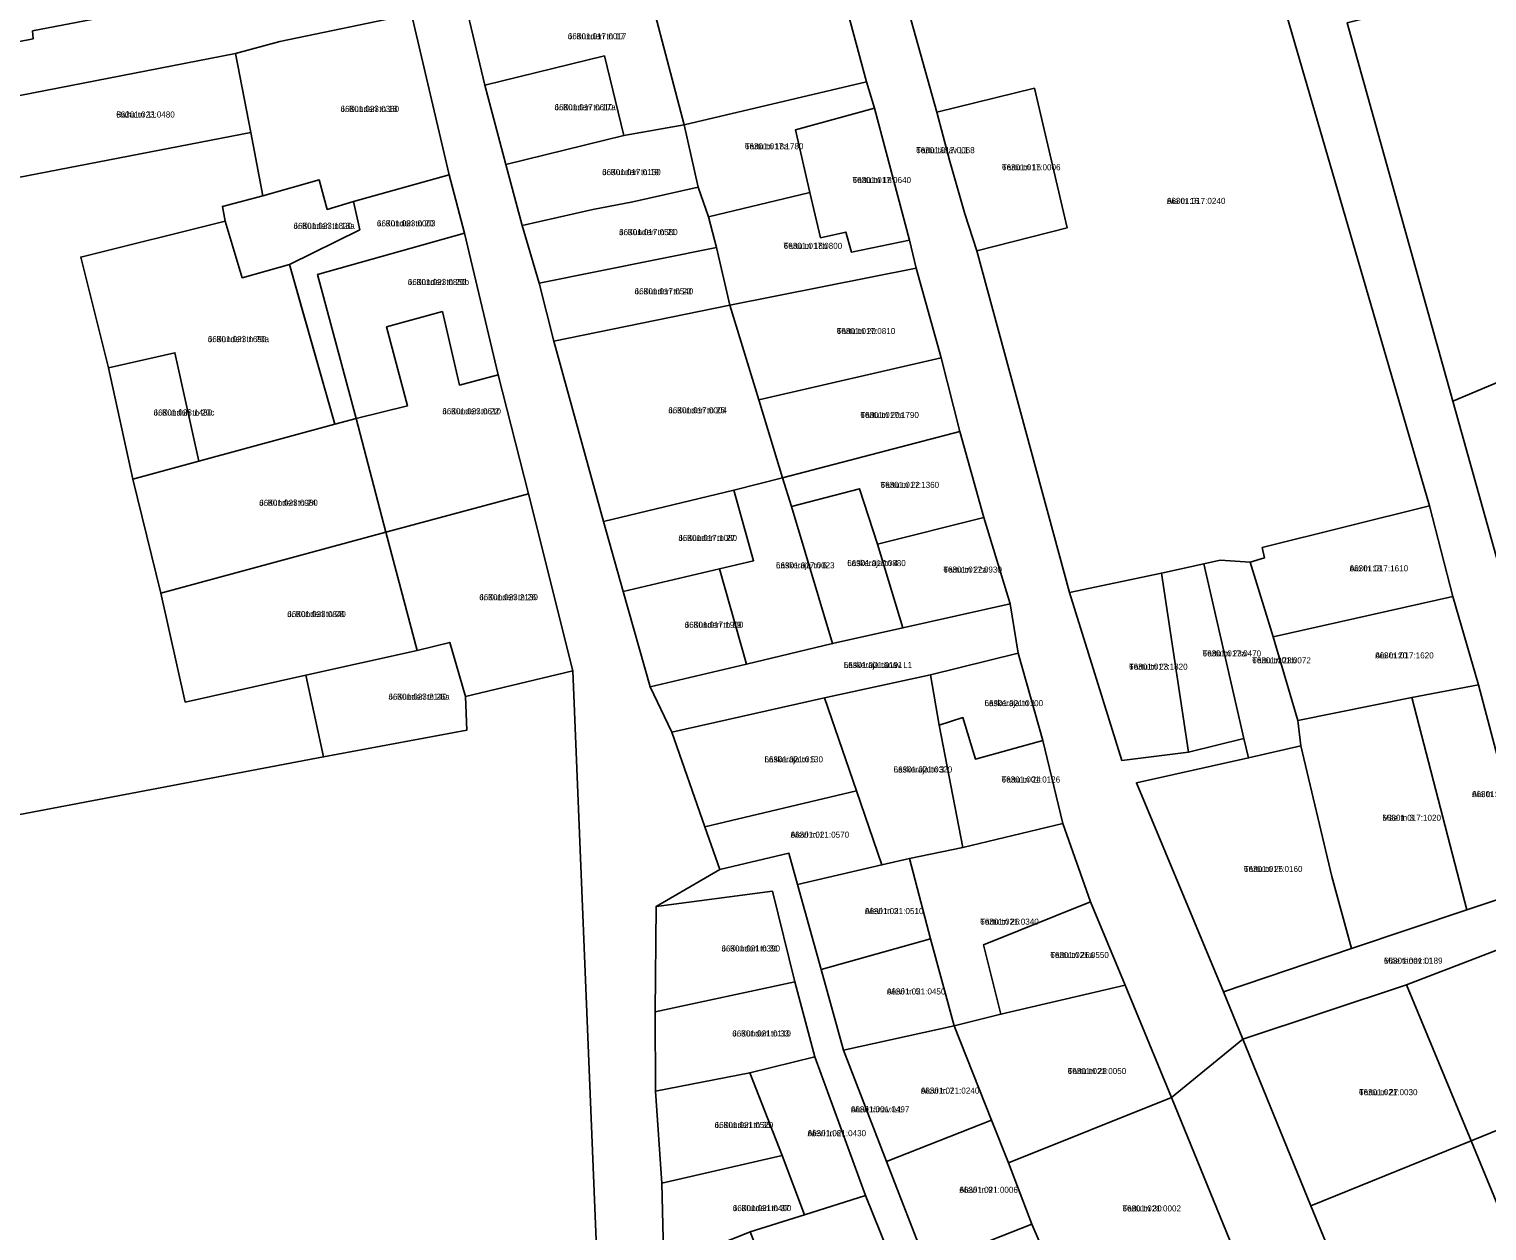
# Model space of a CAD drawing. Extents: x 632278 to 636344, y 6578401 to 6583362.
# Drawn here: x 634102 to 634463, y 6579613.5 to 6579911.1 of the extents above; entities that cross this region are included whole.
import ezdxf

# ---------------------------------------------------------------- set-up
doc = ezdxf.new("R2010")
doc.units = 0
for name, color, linetype in [('L_AADRESS', 7, 'Continuous'), ('PIIR', 7, 'Continuous'), ('TUNNUS', 7, 'Continuous')]:
    doc.layers.add(name, color=color, linetype=linetype)

msp = doc.modelspace()

# ---------------------------------------------------------------- linework, layer by layer
at = {"layer": 'PIIR'}
for points in [[(634134.84, 6579916.78), (634102.89, 6579910.69), (634103.07, 6579908.73), (633996.04, 6579887.8), (633922.52, 6579873.28), (633909.78, 6579870.79), (633882.41, 6579868.19), (633860.88, 6579866.54), (633901.14, 6579996.08)], [(634428.41, 6579912.71), (634454.6, 6579819), (634466.88, 6579774.98), (634471.39, 6579758.77), (634473.81, 6579750.16), (634478.25, 6579733.1), (634483.64, 6579714.01), (634474.24, 6579698.34), (634460.96, 6579748.73), (634454.56, 6579770.62), (634448.82, 6579793.07), (634399.59, 6579962.17)], [(634318.74, 6579919.57), (634326.8, 6579890.54), (634329.99, 6579878.64), (634333.71, 6579865.41), (634336.71, 6579856.24), (634359.7, 6579771.6), (634372.64, 6579730.02), (634389.13, 6579732.08), (634402.81, 6579735.45), (634404.02, 6579730.64), (634376.23, 6579724.48), (634397.83, 6579672.68), (634402.59, 6579661.02), (634384.96, 6579646.58), (634373.45, 6579674.32), (634364.9, 6579695.03), (634357.98, 6579714.38), (634353.05, 6579734.97), (634346.92, 6579756.57), (634344.96, 6579768.8), (634338.49, 6579790.21), (634332.49, 6579811.45), (634327.93, 6579829.68), (634321.67, 6579851.92), (634320.07, 6579858.85), (634311.36, 6579891.55), (634309.43, 6579898.1), (634297.75, 6579941.29)], [(634208.5, 6579923.96), (634214.86, 6579897.24), (634220.1, 6579877.59), (634224.11, 6579862.47), (634228.31, 6579848.23), (634232.01, 6579833.88), (634244.23, 6579789.21), (634249.14, 6579771.82), (634255.8, 6579748.25), (634261.17, 6579737.02), (634269.37, 6579713.57), (634273.06, 6579703.04), (634257.3, 6579693.87), (634257.06, 6579667.79), (634257.18, 6579648.14), (634258.69, 6579625.33), (634259.21, 6579604.65)], [(634257.85, 6579257.23), (634244.2, 6579568.83), (634236.65, 6579752.17), (634225.68, 6579796.06), (634218.2, 6579825.48), (634209.86, 6579860.59), (634206.07, 6579875.04), (634196.71, 6579914.79)], [(634486.34, 6579385.27), (634483.98, 6579405.6), (634478.47, 6579419.65), (634466.61, 6579447.62), (634455.32, 6579474.96), (634438.73, 6579515.02), (634431.09, 6579534.13), (634422.81, 6579554.17), (634417.18, 6579567.08), (634402.17, 6579603.44), (634400.91, 6579607.29), (634384.96, 6579646.58), (634402.59, 6579661.02), (634419.47, 6579619.73), (634437.36, 6579576.09), (634451.81, 6579540.83), (634467.43, 6579502.09), (634483.75, 6579461.64), (634500.06, 6579421.57), (634505.81, 6579408.32), (634509.22, 6579376.05)]]:
    msp.add_lwpolyline(points, dxfattribs=at)
for points in [[(634382.42, 6579776.42), (634359.7, 6579771.6), (634336.71, 6579856.24), (634359.1, 6579861.95), (634351, 6579896.5), (634326.8, 6579890.54), (634318.74, 6579919.57), (634352.27, 6579930.21), (634346.01, 6579951.31), (634399.59, 6579962.17), (634448.82, 6579793.07), (634407.4, 6579782.73), (634407.97, 6579780.21), (634404.38, 6579779.12), (634397, 6579779.58), (634392.91, 6579778.67)], [(634557.59, 6579862.31), (634500.94, 6579838.5), (634454.6, 6579819), (634428.41, 6579912.71), (634517.24, 6579934.89), (634533.05, 6579938.89), (634548.8, 6579942.83), (634554.62, 6579929.91), (634556.45, 6579925.73), (634570.22, 6579894.2), (634579.92, 6579871.87)], [(634252.46, 6579932.45), (634297.75, 6579941.29), (634309.43, 6579898.1), (634264.28, 6579887.44)], [(634208.5, 6579923.96), (634252.46, 6579932.45), (634264.28, 6579887.44), (634249.32, 6579884.78), (634244.48, 6579904.5), (634214.86, 6579897.24)], [(634192.49, 6579928.96), (634196.71, 6579914.79), (634164.1, 6579908.1), (634153.15, 6579905.08), (634090.32, 6579892.84), (634029.4, 6579880.96), (634021.71, 6579879.31), (633974.52, 6579871.4), (633934.61, 6579863.15), (633916.66, 6579859.34), (633920.26, 6579867.83), (633922.52, 6579873.28), (633996.04, 6579887.8), (634103.07, 6579908.73), (634102.89, 6579910.69), (634134.84, 6579916.78)], [(634182.33, 6579868.42), (634175.85, 6579866.48), (634173.86, 6579873.76), (634159.93, 6579869.82), (634156.91, 6579885.52), (634153.15, 6579905.08), (634164.1, 6579908.1), (634196.71, 6579914.79), (634206.07, 6579875.04)], [(634090.32, 6579892.84), (634153.15, 6579905.08), (634156.91, 6579885.52), (634094.14, 6579873.38)], [(634214.86, 6579897.24), (634244.48, 6579904.5), (634249.32, 6579884.78), (634220.1, 6579877.59)], [(634267.75, 6579871.97), (634264.28, 6579887.44), (634309.43, 6579898.1), (634311.36, 6579891.55), (634291.8, 6579886.18), (634295.39, 6579870.63), (634270.28, 6579864.63)], [(634326.8, 6579890.54), (634351, 6579896.5), (634359.1, 6579861.95), (634336.71, 6579856.24), (634333.71, 6579865.41), (634329.99, 6579878.64)], [(634311.36, 6579891.55), (634320.07, 6579858.85), (634305.68, 6579855.88), (634304.28, 6579860.86), (634298.03, 6579859.46), (634295.39, 6579870.63), (634291.8, 6579886.18)], [(633987.22, 6579804.58), (634000.93, 6579805.97), (634034.81, 6579812.6), (634023.21, 6579872.13), (634021.71, 6579879.31), (634029.4, 6579880.96), (634033.39, 6579860.17), (634043.31, 6579862.03), (634042.99, 6579863.24), (634094.14, 6579873.38), (634156.91, 6579885.52), (634159.93, 6579869.82), (634149.88, 6579867.2), (634150.61, 6579863.55), (634114.83, 6579854.66), (634121.68, 6579827.26), (634127.73, 6579799.67), (634134.62, 6579771.46), (634140.69, 6579744.46), (634170.57, 6579751.11), (634174.97, 6579730.89), (634055.35, 6579708.17), (634050.52, 6579730.42), (634002.77, 6579717.78)], [(634220.1, 6579877.59), (634249.32, 6579884.78), (634264.28, 6579887.44), (634267.75, 6579871.97), (634251.55, 6579868.38), (634241.63, 6579866.44), (634224.11, 6579862.47)], [(634206.07, 6579875.04), (634209.86, 6579860.59), (634173.43, 6579850.38), (634183.06, 6579814.7), (634177.74, 6579813.26), (634166.48, 6579852.84), (634183.89, 6579861.43), (634182.33, 6579868.42)], [(634150.61, 6579863.55), (634149.88, 6579867.2), (634159.93, 6579869.82), (634173.86, 6579873.76), (634175.85, 6579866.48), (634182.33, 6579868.42), (634183.89, 6579861.43), (634166.48, 6579852.84), (634154.79, 6579849.55)], [(634224.11, 6579862.47), (634241.63, 6579866.44), (634251.55, 6579868.38), (634267.75, 6579871.97), (634270.28, 6579864.63), (634272.24, 6579857.03), (634228.31, 6579848.23)], [(634272.24, 6579857.03), (634270.28, 6579864.63), (634295.39, 6579870.63), (634298.03, 6579859.46), (634304.28, 6579860.86), (634305.68, 6579855.88), (634320.07, 6579858.85), (634321.67, 6579851.92), (634275.58, 6579842.77)], [(634138.12, 6579830.98), (634121.68, 6579827.26), (634114.83, 6579854.66), (634150.61, 6579863.55), (634154.79, 6579849.55), (634166.48, 6579852.84), (634169.65, 6579841.7), (634177.74, 6579813.26), (634144.05, 6579804.11)], [(634195.71, 6579817.81), (634183.06, 6579814.7), (634173.43, 6579850.38), (634209.86, 6579860.59), (634218.2, 6579825.48), (634208.62, 6579822.97), (634204.38, 6579841.18), (634190.54, 6579837.41)], [(634275.58, 6579842.77), (634232.01, 6579833.88), (634228.31, 6579848.23), (634272.24, 6579857.03)], [(634275.58, 6579842.77), (634321.67, 6579851.92), (634327.93, 6579829.68), (634282.76, 6579819.29)], [(634232.01, 6579833.88), (634275.58, 6579842.77), (634282.76, 6579819.29), (634288.57, 6579799.96), (634276.53, 6579796.91), (634244.23, 6579789.21)], [(634204.38, 6579841.18), (634208.62, 6579822.97), (634218.2, 6579825.48), (634225.68, 6579796.06), (634190.4, 6579786.55), (634183.06, 6579814.7), (634195.71, 6579817.81), (634190.54, 6579837.41)], [(634454.6, 6579819), (634500.94, 6579838.5), (634517.72, 6579795.77), (634466.88, 6579774.98)], [(634121.68, 6579827.26), (634138.12, 6579830.98), (634144.05, 6579804.11), (634127.73, 6579799.67)], [(634282.76, 6579819.29), (634327.93, 6579829.68), (634332.49, 6579811.45), (634288.57, 6579799.96)], [(634127.73, 6579799.67), (634144.05, 6579804.11), (634177.74, 6579813.26), (634183.06, 6579814.7), (634190.4, 6579786.55), (634134.62, 6579771.46)], [(634307.65, 6579797.31), (634290.81, 6579792.93), (634288.57, 6579799.96), (634332.49, 6579811.45), (634338.49, 6579790.21), (634312.09, 6579783.58)], [(634236.65, 6579752.17), (634244.2, 6579568.83), (634195.23, 6579557.18), (634189.1, 6579582.52), (634151.76, 6579574.54), (634002.4, 6579543.18), (633848.98, 6579582.11), (633909.28, 6579792.9), (633961.16, 6579778.11), (633970.17, 6579802.87), (633987.22, 6579804.58), (634002.77, 6579717.78), (634050.52, 6579730.42), (634055.35, 6579708.17), (634174.97, 6579730.89), (634210.42, 6579737.49), (634210.12, 6579745.81)], [(634279.65, 6579753.89), (634272.98, 6579777.46), (634281.45, 6579779.47), (634276.53, 6579796.91), (634288.57, 6579799.96), (634290.81, 6579792.93), (634301.01, 6579758.95)], [(634206.2, 6579759.23), (634198.15, 6579757.25), (634190.4, 6579786.55), (634225.68, 6579796.06), (634236.65, 6579752.17), (634210.12, 6579745.81)], [(634276.53, 6579796.91), (634281.45, 6579779.47), (634272.98, 6579777.46), (634249.14, 6579771.82), (634244.23, 6579789.21)], [(634290.81, 6579792.93), (634307.65, 6579797.31), (634312.09, 6579783.58), (634318.42, 6579762.85), (634301.01, 6579758.95)], [(634404.38, 6579779.12), (634407.97, 6579780.21), (634407.4, 6579782.73), (634448.82, 6579793.07), (634454.56, 6579770.62), (634410.09, 6579760.61)], [(634312.09, 6579783.58), (634338.49, 6579790.21), (634344.96, 6579768.8), (634318.42, 6579762.85)], [(634198.15, 6579757.25), (634170.57, 6579751.11), (634140.69, 6579744.46), (634134.62, 6579771.46), (634190.4, 6579786.55)], [(634249.14, 6579771.82), (634272.98, 6579777.46), (634279.65, 6579753.89), (634255.8, 6579748.25)], [(634359.7, 6579771.6), (634382.42, 6579776.42), (634389.13, 6579732.08), (634372.64, 6579730.02)], [(634382.42, 6579776.42), (634392.91, 6579778.67), (634402.81, 6579735.45), (634389.13, 6579732.08)], [(634402.81, 6579735.45), (634392.91, 6579778.67), (634397, 6579779.58), (634404.38, 6579779.12), (634410.09, 6579760.61), (634416.22, 6579739.94), (634416.98, 6579733.67), (634404.02, 6579730.64)], [(634410.09, 6579760.61), (634454.56, 6579770.62), (634460.96, 6579748.73), (634444.46, 6579745.56), (634416.22, 6579739.94)], [(634255.8, 6579748.25), (634279.65, 6579753.89), (634301.01, 6579758.95), (634318.42, 6579762.85), (634344.96, 6579768.8), (634346.92, 6579756.57), (634325.28, 6579751.25), (634298.98, 6579745.49), (634261.17, 6579737.02)], [(634170.57, 6579751.11), (634198.15, 6579757.25), (634206.2, 6579759.23), (634210.12, 6579745.81), (634210.42, 6579737.49), (634174.97, 6579730.89)], [(634346.92, 6579756.57), (634353.05, 6579734.97), (634336.38, 6579730.36), (634333.26, 6579740.62), (634327.42, 6579738.76), (634325.28, 6579751.25)], [(634306.91, 6579722.45), (634298.98, 6579745.49), (634325.28, 6579751.25), (634327.42, 6579738.76), (634333.27, 6579708.46), (634320.06, 6579705.69), (634313.21, 6579704.15)], [(634460.96, 6579748.73), (634474.24, 6579698.34), (634458.09, 6579693.02), (634444.46, 6579745.56)], [(634269.37, 6579713.57), (634261.17, 6579737.02), (634298.98, 6579745.49), (634306.91, 6579722.45)], [(634424.64, 6579701.3), (634416.98, 6579733.67), (634416.22, 6579739.94), (634444.46, 6579745.56), (634458.09, 6579693.02), (634429.51, 6579683.46)], [(634353.05, 6579734.97), (634357.98, 6579714.38), (634333.27, 6579708.46), (634327.42, 6579738.76), (634333.26, 6579740.62), (634336.38, 6579730.36)], [(634404.02, 6579730.64), (634416.98, 6579733.67), (634424.64, 6579701.3), (634429.51, 6579683.46), (634397.83, 6579672.68), (634376.23, 6579724.48)], [(634269.37, 6579713.57), (634306.91, 6579722.45), (634313.21, 6579704.15), (634292.32, 6579699.31), (634290.19, 6579707.02), (634273.06, 6579703.04)], [(634342.7, 6579667.14), (634331.14, 6579664.3), (634325.25, 6579685.85), (634320.06, 6579705.69), (634333.27, 6579708.46), (634357.98, 6579714.38), (634364.9, 6579695.03), (634338.37, 6579684.33)], [(634286.12, 6579697.6), (634257.3, 6579693.87), (634273.06, 6579703.04), (634290.19, 6579707.02), (634292.32, 6579699.31), (634298.16, 6579678.23), (634303.74, 6579658.25), (634314.39, 6579630.69), (634324.34, 6579604.93), (634350.34, 6579615.16), (634353.75, 6579607.34), (634317.53, 6579593.31), (634288.73, 6579581.97), (634260.69, 6579570.94), (634260.34, 6579581.21), (634273.65, 6579584.83), (634288.77, 6579592.51), (634316.72, 6579603.45), (634309.12, 6579622.23), (634296.58, 6579656.65), (634291.63, 6579675.15)], [(634292.32, 6579699.31), (634313.21, 6579704.15), (634320.06, 6579705.69), (634325.25, 6579685.85), (634298.16, 6579678.23)], [(634257.3, 6579693.87), (634286.12, 6579697.6), (634291.63, 6579675.15), (634257.06, 6579667.79)], [(634397.83, 6579672.68), (634429.51, 6579683.46), (634458.09, 6579693.02), (634474.24, 6579698.34), (634478.82, 6579688.15), (634443.11, 6579674.48), (634402.58, 6579661.02)], [(634338.37, 6579684.33), (634364.9, 6579695.03), (634373.45, 6579674.32), (634342.7, 6579667.14)], [(634443.11, 6579674.48), (634478.82, 6579688.15), (634498.89, 6579652.01), (634459.11, 6579635.82)], [(634298.16, 6579678.23), (634325.25, 6579685.85), (634331.14, 6579664.3), (634303.74, 6579658.25)], [(634291.63, 6579675.15), (634296.58, 6579656.65), (634280.49, 6579652.67), (634257.18, 6579648.14), (634257.06, 6579667.79)], [(634384.96, 6579646.58), (634344.56, 6579630.35), (634340.39, 6579640.92), (634331.14, 6579664.3), (634342.7, 6579667.14), (634373.45, 6579674.32)], [(634402.59, 6579661.02), (634443.11, 6579674.48), (634459.11, 6579635.82), (634419.47, 6579619.73)], [(634303.74, 6579658.25), (634331.14, 6579664.3), (634340.39, 6579640.92), (634314.39, 6579630.69)], [(634288.48, 6579632.15), (634280.49, 6579652.67), (634296.58, 6579656.65), (634309.12, 6579622.23), (634294.06, 6579617.48)], [(634257.18, 6579648.14), (634280.49, 6579652.67), (634288.48, 6579632.15), (634258.69, 6579625.33)], [(634507.7, 6579630.53), (634468.21, 6579613.76), (634459.11, 6579635.82), (634498.89, 6579652.01)], [(634344.56, 6579630.35), (634384.96, 6579646.58), (634400.91, 6579607.29), (634360.93, 6579590.05), (634353.75, 6579607.34), (634350.34, 6579615.16)], [(634314.39, 6579630.69), (634340.39, 6579640.92), (634344.56, 6579630.35), (634350.34, 6579615.16), (634324.34, 6579604.93)], [(634437.36, 6579576.09), (634419.47, 6579619.73), (634459.11, 6579635.82), (634468.21, 6579613.76), (634475.38, 6579596.51), (634476.99, 6579592.37)], [(634258.69, 6579625.33), (634288.48, 6579632.15), (634294.06, 6579617.48), (634280.62, 6579613.27), (634259.21, 6579604.65)], [(634288.77, 6579592.51), (634280.62, 6579613.27), (634294.06, 6579617.48), (634309.12, 6579622.23), (634316.72, 6579603.45)]]:
    msp.add_lwpolyline(points, close=True, dxfattribs=at)

# ---------------------------------------------------------------- texts
at = {"layer": 'L_AADRESS'}
for s, p in [('J. Kunderi tn 17', (634235.44, 6579908.62)), ('J. Kunderi tn 18', (634179.16, 6579890.63)), ('J. Kunderi tn 17a', (634232.15, 6579891.04)), ('Rahu tn 11', (634123.61, 6579889.23)), ('Tartu tn 18a', (634279.28, 6579881.37)), ('Tartu tänav L1', (634321.69, 6579880.4)), ('Tartu tn 15', (634342.95, 6579876.17)), ('J. Kunderi tn 19', (634243.94, 6579874.96)), ('Tartu tn 18', (634305.93, 6579873)), ('Aia tn 16', (634383.78, 6579867.84)), ('J. Kunderi tn 18a', (634167.51, 6579861.66)), ('J. Kunderi tn 20', (634188.17, 6579862.28)), ('J. Kunderi tn 21', (634248.13, 6579860.1)), ('Tartu tn 18b', (634288.88, 6579856.7)), ('J. Kunderi tn 20b', (634195.82, 6579847.75)), ('J. Kunderi tn 23', (634251.99, 6579845.46)), ('J. Kunderi tn 20a', (634146.29, 6579833.6)), ('Tartu tn 20', (634302.02, 6579835.61)), ('J. Kunderi tn 20c', (634132.86, 6579815.43)), ('J. Kunderi tn 22', (634204.37, 6579815.75)), ('J. Kunderi tn 25', (634260.33, 6579815.99)), ('Tartu tn 20a', (634307.88, 6579814.82)), ('Tartu tn 22', (634312.89, 6579797.51)), ('J. Kunderi tn 24', (634159.02, 6579793.08)), ('J. Kunderi tn 27', (634262.83, 6579784.37)), ('Laskeraja tn 6', (634286.99, 6579777.6)), ('Laskeraja tn 4', (634304.62, 6579778.14)), ('Tartu tn 22a', (634328.43, 6579776.53)), ('Aia tn 18', (634429.03, 6579776.84)), ('J. Kunderi tn 26', (634213.52, 6579769.7)), ('J. Kunderi tn 28', (634165.96, 6579765.51)), ('J. Kunderi tn 29', (634264.39, 6579762.86)), ('Tartu tn 23a', (634392.62, 6579755.77)), ('Tartu tn 23b', (634404.94, 6579754.07)), ('Aia tn 20', (634435.36, 6579755.28)), ('Laskeraja tänav L1', (634303.77, 6579752.91)), ('Tartu tn 23', (634374.42, 6579752.48)), ('J. Kunderi tn 26a', (634191.02, 6579745.06)), ('Laskeraja tn 1', (634338.63, 6579743.46)), ('Laskeraja tn 5', (634284.13, 6579729.53)), ('Laskeraja tn 3', (634316.12, 6579727.03)), ('Tartu tn 24', (634342.86, 6579724.54)), ('Aia tn 22', (634459.35, 6579720.93)), ('Mäe tn 3', (634437.16, 6579715.06)), ('Alevi tn 1', (634290.6, 6579710.88)), ('Tartu tn 25', (634402.87, 6579702.39)), ('Alevi tn 3', (634309, 6579691.96)), ('Tartu tn 26', (634337.56, 6579689.34)), ('J. Kunderi tn 31', (634273.49, 6579682.7)), ('Tartu tn 26a', (634354.92, 6579681.09)), ('Mäe tänav L1', (634437.55, 6579679.68)), ('Alevi tn 5', (634314.45, 6579672.05)), ('J. Kunderi tn 33', (634276.17, 6579661.65)), ('Tartu tn 28', (634359.22, 6579652.34)), ('Alevi tn 7', (634322.84, 6579647.5)), ('Tartu tn 27', (634431.36, 6579647.11)), ('Alevi tänav L1', (634305.52, 6579642.86)), ('J. Kunderi tn 35', (634271.8, 6579639)), ('Alevi tn 6', (634294.8, 6579636.96)), ('Alevi tn 9', (634332.39, 6579622.93)), ('J. Kunderi tn 37', (634276.29, 6579618.4)), ('Tartu tn 30', (634372.79, 6579618.32))]:
    msp.add_text(s, height=1.5, dxfattribs=at).set_placement(p)
at = {"layer": 'TUNNUS'}
for s, p in [('66301:017:0017', (634235.44, 6579908.62)), ('66301:023:0380', (634179.16, 6579890.63)), ('66301:017:0610', (634232.15, 6579891.04)), ('66301:023:0480', (634123.61, 6579889.23)), ('66301:017:1780', (634279.28, 6579881.37)), ('66301:017:0068', (634321.69, 6579880.4)), ('66301:017:0006', (634342.95, 6579876.17)), ('66301:017:0130', (634243.94, 6579874.96)), ('66301:017:0640', (634305.93, 6579873)), ('66301:017:0240', (634383.78, 6579867.84)), ('66301:023:1820', (634167.51, 6579861.66)), ('66301:023:0003', (634188.17, 6579862.28)), ('66301:017:0580', (634248.13, 6579860.1)), ('66301:017:0800', (634288.88, 6579856.7)), ('66301:023:0850', (634195.82, 6579847.75)), ('66301:017:0540', (634251.99, 6579845.46)), ('66301:023:1690', (634146.29, 6579833.6)), ('66301:017:0810', (634302.02, 6579835.61)), ('66301:023:1480', (634132.86, 6579815.43)), ('66301:023:0610', (634204.37, 6579815.75)), ('66301:017:0004', (634260.33, 6579815.99)), ('66301:017:1790', (634307.88, 6579814.82)), ('66301:017:1360', (634312.89, 6579797.51)), ('66301:023:0980', (634159.02, 6579793.08)), ('66301:017:1080', (634262.83, 6579784.37)), ('66301:017:0023', (634286.99, 6579777.6)), ('66301:017:0880', (634304.62, 6579778.14)), ('66301:017:0930', (634328.43, 6579776.53)), ('66301:017:1610', (634429.03, 6579776.84)), ('66301:023:2130', (634213.52, 6579769.7)), ('66301:023:0840', (634165.96, 6579765.51)), ('66301:017:1900', (634264.39, 6579762.86)), ('66301:017:0470', (634392.62, 6579755.77)), ('66301:001:0072', (634404.94, 6579754.07)), ('66301:017:1620', (634435.36, 6579755.28)), ('66301:001:0191', (634303.77, 6579752.91)), ('66301:017:1820', (634374.42, 6579752.48)), ('66301:023:2140', (634191.02, 6579745.06)), ('66301:021:0100', (634338.63, 6579743.46)), ('66301:021:0130', (634284.13, 6579729.53)), ('66301:021:0320', (634316.12, 6579727.03)), ('66301:001:0126', (634342.86, 6579724.54)), ('66301:017:0001', (634459.35, 6579720.93)), ('66301:017:1020', (634437.16, 6579715.06)), ('66301:021:0570', (634290.6, 6579710.88)), ('66301:017:0160', (634402.87, 6579702.39)), ('66301:021:0510', (634309, 6579691.96)), ('66301:021:0340', (634337.56, 6579689.34)), ('66301:021:0390', (634273.49, 6579682.7)), ('66301:021:0550', (634354.92, 6579681.09)), ('66301:001:0189', (634437.55, 6579679.68)), ('66301:021:0450', (634314.45, 6579672.05)), ('66301:021:0110', (634276.17, 6579661.65)), ('66301:021:0050', (634359.22, 6579652.34)), ('66301:021:0240', (634322.84, 6579647.5)), ('66301:021:0030', (634431.36, 6579647.11)), ('66301:001:0497', (634305.52, 6579642.86)), ('66301:021:0520', (634271.8, 6579639)), ('66301:021:0430', (634294.8, 6579636.96)), ('66301:021:0006', (634332.39, 6579622.93)), ('66301:021:0400', (634276.29, 6579618.4)), ('66301:021:0002', (634372.79, 6579618.32))]:
    msp.add_text(s, height=1.5, dxfattribs=at).set_placement(p)

doc.saveas('drawing.dxf')
